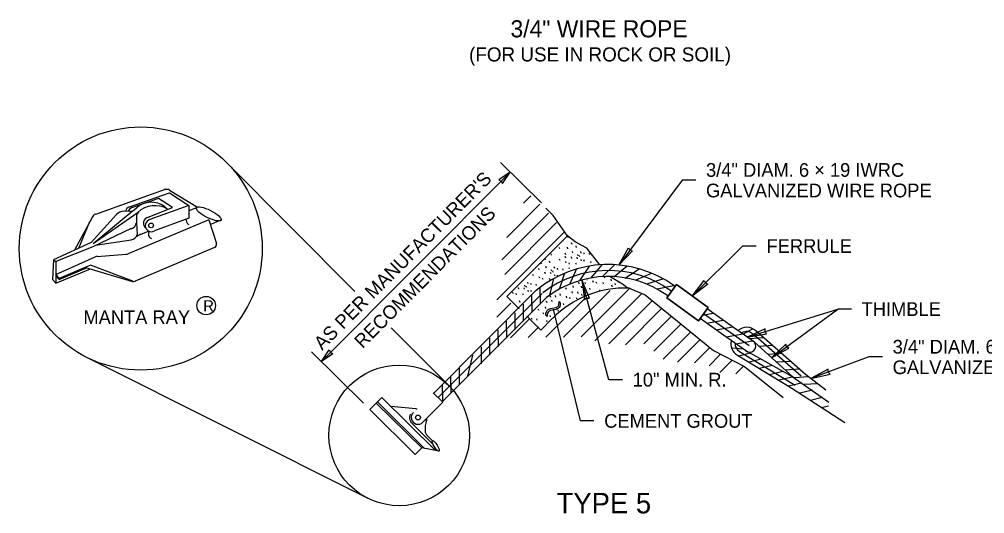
# Model space of a CAD drawing. Extents: x 99861 to 103151, y 100000 to 102076.
# Drawn here: x 101375 to 102504, y 100899 to 101477 of the extents above; entities that cross this region are included whole.
import ezdxf

# ---------------------------------------------------------------- set-up
doc = ezdxf.new("R2010")
doc.units = 0
for name, color, linetype in [('Level 1', 7, 'Continuous'), ('Level 10', 7, 'Continuous'), ('Level 15', 7, 'Continuous'), ('Level 18', 7, 'Continuous'), ('Level 2', 7, 'Continuous'), ('Level 20', 7, 'Continuous'), ('Level 4', 7, 'Continuous'), ('Level 6', 7, 'Continuous'), ('Level 8', 7, 'Continuous')]:
    doc.layers.add(name, color=color, linetype=linetype)

msp = doc.modelspace()

# ---------------------------------------------------------------- linework, layer by layer
at = {"layer": 'Level 1'}
for p, q in [((101859.9, 101040.3), (101979.4, 101160.2)), ((101991.7, 101152.1), (101869.9, 101030.4)), ((102280.2, 101059), (102224.6, 101090.1)), ((102235, 101099.8), (102280.2, 101059)), ((102279.2, 101059.7), (102322.1, 101029.8))]:
    msp.add_line(p, q, dxfattribs=at)
for points in [[(102138, 101159.4), (102136.5, 101160.5)], [(102142.1, 101165.1), (102140.5, 101166.2)], [(102133.9, 101153.7), (102132.5, 101154.7)], [(102234.9, 101099.9), (102206.7, 101119.8), (102179.6, 101138.8)], [(102224.6, 101090.1), (102198.7, 101108.3), (102171.4, 101127.5)], [(102318.3, 101043.9), (102294.8, 101062.2), (102236.6, 101113)], [(102215, 101084.7), (102278.5, 101046.3), (102340.8, 101006)]]:
    msp.add_lwpolyline(points, dxfattribs=at)
for centre, radius, start, end in [((102063.9, 101058.4), 132.3, 54.6068, 129.6692), ((102063.9, 101058.4), 118.3, 54.565, 127.6505), ((102225.8, 101101.5), 15.8, 47.0914, 130.0304), ((102222.7, 101097.9), 15.3, 165.1513, 239.931), ((102229.5, 101095.3), 7.15, 226.812, 38.9693)]:
    msp.add_arc(centre, radius, start, end, dxfattribs=at)
at = {"layer": 'Level 10'}
for p, q in [((101964.9, 101262.3), (101973.5, 101271)), ((101964.9, 101262.3), (101973.5, 101271)), ((101945.2, 101222.3), (101984, 101261.1)), ((101939.4, 101196.1), (101994.2, 101250.9)), ((101942.9, 101179.2), (102003.5, 101239.8)), ((101942.9, 101179.2), (102003.5, 101239.8)), ((101933.5, 101149.4), (102012.7, 101228.7)), ((102011.6, 101105.8), (102066.3, 101160.5)), ((102011.6, 101105.8), (102066.3, 101160.5)), ((102032.2, 101106), (102089.6, 101163.5)), ((101933.5, 101129), (101950, 101145.6)), ((101991, 101105.6), (102036.9, 101151.5)), ((102048.2, 101101.6), (102102.9, 101156.4)), ((102064.8, 101097.9), (102115.3, 101148.4)), ((102064.8, 101097.9), (102115.3, 101148.4)), ((102084.2, 101096.9), (102126.4, 101139.2)), ((101949.5, 101105.1), (101971.8, 101127.1)), ((101949.5, 101105.1), (101971.8, 101127.1)), ((102105.5, 101097.9), (102137.5, 101129.9)), ((101970.4, 101105.3), (101982.1, 101117)), ((102117.4, 101089.4), (102148.6, 101120.6)), ((102117.4, 101089.4), (102148.6, 101120.6)), ((102128.3, 101080), (102159.7, 101111.4)), ((102145.1, 101076.4), (102170.8, 101102.1)), ((102165, 101075.9), (102181.9, 101092.8)), ((102165, 101075.9), (102181.9, 101092.8)), ((102181.8, 101072.3), (102194.9, 101085.4)), ((102194.3, 101064.4), (102208.4, 101078.6)), ((102213.2, 101063), (102222, 101071.8)), ((102213.2, 101063), (102222, 101071.8))]:
    msp.add_line(p, q, dxfattribs=at)
at = {"layer": 'Level 15'}
for p, q in [((101617.7, 101309.7), (101767.7, 101159.3)), ((101985.9, 101262.6), (101937.8, 101309.9)), ((101949.3, 101298.6), (101728.4, 101077.4)), ((102150.3, 101289.2), (102076.2, 101190.1)), ((102166.3, 101289.2), (102150.3, 101289.2)), ((102162.2, 101153.8), (102221.1, 101212.3)), ((102237.1, 101212.3), (102221.1, 101212.3)), ((102064.5, 101056.1), (102033.1, 101172.6)), ((101999.4, 101138.6), (102031.2, 101007.9)), ((102226.6, 101105.8), (102332.3, 101138.6)), ((102255, 101081.8), (102332.3, 101138.6)), ((102348.3, 101138.6), (102332.3, 101138.6)), ((101810.1, 101116.8), (101877.6, 101049.1)), ((101453.5, 101082.3), (101782.6, 100917.5)), ((101777.8, 101028.8), (101717, 101088.7)), ((102368.6, 101082.6), (102300.9, 101057.4)), ((102384.6, 101082.6), (102368.6, 101082.6)), ((102080.5, 101056.1), (102064.5, 101056.1)), ((102047.2, 101007.9), (102031.2, 101007.9))]:
    msp.add_line(p, q, dxfattribs=at)
for points in [[(101949.3, 101298.6), (101936, 101289.7), (101938.7, 101288), (101940.4, 101285.3)], [(102076.2, 101190.1), (102087.5, 101210.1), (102089.2, 101207.5), (102092.3, 101206.6)], [(102033.1, 101172.6), (102036.1, 101149.8), (102038.7, 101151.5), (102041.9, 101151.3)], [(102162.2, 101153.8), (102176.3, 101172), (102177.6, 101169.2), (102180.5, 101167.8)], [(102226.6, 101105.8), (102249.2, 101109.7), (102247.4, 101112.3), (102247.5, 101115.4)], [(101728.4, 101077.4), (101737.3, 101090.8), (101739, 101088.1), (101741.7, 101086.4)], [(102255, 101081.8), (102275.1, 101092.9), (102272.5, 101094.7), (102271.6, 101097.7)], [(102300.9, 101057.4), (102323.4, 101062.6), (102321.3, 101065), (102321.3, 101068.2)]]:
    msp.add_lwpolyline(points, close=True, dxfattribs=at)
for centre, radius in [((101517.1, 101209.4), 142.1), ((101819.4, 100991), 82.2)]:
    msp.add_circle(centre, radius, dxfattribs=at)
at = {"layer": 'Level 2'}
for p, q in [((101515.7, 101259.7), (101509.3, 101254.4)), ((101506.8, 101252.4), (101461.4, 101214.9)), ((101512.8, 101250.6), (101461.4, 101214.9)), ((101582.3, 101257), (101573.2, 101253.3)), ((101460.6, 101246.3), (101439.6, 101207.5)), ((101444.8, 101209.8), (101457.6, 101240.8)), ((101610.9, 101242.4), (101598.5, 101237.3)), ((101526.5, 101229.6), (101517, 101225.9)), ((102016.4, 101224.2), (101945.4, 101153.2)), ((101417.6, 101194.4), (101417.6, 101172.8)), ((101421.6, 101173.3), (101453.5, 101187)), ((101959.9, 101138.9), (101945.4, 101153.2)), ((101985.1, 101114.1), (101968.7, 101130.2)), ((101985.1, 101114.1), (101998.9, 101128.1)), ((101793.1, 101029.3), (101799, 101035.2)), ((101861.8, 100973.3), (101799, 101035.2)), ((101870.5, 101029.8), (101859.2, 101040.9)), ((101785.1, 101021.3), (101793.1, 101029.3)), ((101838.1, 100968.5), (101785.1, 101021.3)), ((101845.9, 100976.4), (101792.6, 101028.8)), ((101849.1, 100975.8), (101793.9, 101030.1)), ((101838.9, 101022), (101809.7, 101024.6)), ((101847.1, 101006.3), (101870.5, 101029.8)), ((101832.9, 101006.5), (101858.8, 100980.9)), ((101858.4, 100984.6), (101852.6, 100990.3)), ((101838.1, 100968.5), (101845.9, 100976.4)), ((101866, 100972.5), (101845.9, 100976.4))]:
    msp.add_line(p, q, dxfattribs=at)
for points in [[(101464.5, 101249.7), (101544.7, 101278.2)], [(101504.1, 101258.2), (101550.7, 101274.5), (101573.2, 101259.7), (101527.9, 101243.2)], [(101550.9, 101277.6), (101583.6, 101257.9)], [(101525.6, 101246), (101554.1, 101257.2), (101537.8, 101267.8), (101506.4, 101256.8)], [(101573.2, 101259.7), (101573.2, 101245), (101533.3, 101230.2)], [(101488.6, 101249), (101459.2, 101216.5), (101415.1, 101196.2)], [(101504.5, 101252.8), (101497.5, 101252.9)], [(102016, 101224.6), (101999.4, 101248.1), (101990.8, 101256.7)], [(101596.8, 101243), (101502.4, 101203.2)], [(101512.1, 101246.8), (101512.1, 101239.8)], [(101512.1, 101239.8), (101512.9, 101225.9)], [(101569.9, 101243.8), (101569.9, 101243.6)], [(101572.5, 101238), (101573.4, 101237.3)], [(101596.8, 101243), (101605.6, 101215.3)], [(101505.8, 101232.6), (101460.9, 101211.4), (101417.6, 101194.4)], [(101526, 101227.2), (101526, 101226.9)], [(101505.8, 101219.3), (101464.2, 101213)], [(101528.7, 101221.4), (101529.5, 101220.7)], [(102053.9, 101190.3), (102038.7, 101209.7), (102025.3, 101217.4), (102016.4, 101224.2)], [(101466.3, 101200.2), (101500.1, 101202.6)], [(101603.4, 101210.4), (101510.6, 101171.3)], [(101415.1, 101196.2), (101413.8, 101173), (101417.6, 101168.8)], [(101415.1, 101196.2), (101417.6, 101194.4)], [(101417.6, 101179.1), (101463.9, 101199.6)], [(101417.6, 101172.8), (101417.6, 101168.8), (101458.3, 101185.5)], [(101417.8, 101181.8), (101417.6, 101179.1), (101421.5, 101174.9)], [(101507.7, 101171.2), (101458.3, 101189.8), (101421.6, 101174.5)], [(101452.6, 101187.2), (101507.4, 101170.9)], [(101421.6, 101174.5), (101421.6, 101173.3), (101417.6, 101177.5)], [(101417.6, 101172.8), (101417.6, 101170.7)], [(102066, 101176.6), (102080.5, 101168.3), (102085.6, 101164.3), (102107, 101155.3)], [(102107, 101155.3), (102187, 101090.1), (102223.5, 101071.5), (102268.5, 101035.4)]]:
    msp.add_lwpolyline(points, dxfattribs=at)
for centre, radius in [((101529.2, 101236.4), 2.74), ((101593.6, 101142.7), 10.8), ((101841.4, 101011.9), 2.88)]:
    msp.add_circle(centre, radius, dxfattribs=at)
for centre, radius, start, end in [((101547.2, 101271.4), 7.2, 59.0362, 109.5852), ((101505.7, 101252.1), 6.32, 104.778, 172.4401), ((101533.7, 101230.6), 28.9, 59.6054, 133.9446), ((101529.2, 101236.4), 27, 45, 120.2173), ((101466.9, 101242.9), 7.2, 109.6041, 151.5571), ((101497.5, 101240.9), 12, 90, 137.7927), ((101508.3, 101251), 6.06, 107.9609, 162.1611), ((101504.7, 101260), 7.2, 268.9234, 309.516), ((101519.3, 101246.8), 7.2, 131.5306, 180), ((101508.7, 101256.5), 7.2, 304.7847, 313.9446), ((101503.4, 101241.1), 8.84, 285.703, 351.7847), ((101527.3, 101238.9), 7.15, 100.4083, 234.4437), ((101529.5, 101236.2), 7.15, 100.4083, 301.5442), ((101577.1, 101243.6), 7.2, 180, 230.5368), ((101504.3, 101228.1), 8.88, 279.9313, 346.013), ((101524.3, 101207.3), 20, 110.8825, 134.4879), ((101533.2, 101226.9), 7.2, 158.16, 230.5368), ((101601.7, 101214.1), 4, 292.8671, 17.488), ((101499.6, 101209.8), 7.2, 274.0406, 292.8671), ((101466.8, 101193.1), 7.2, 94.0406, 113.9625), ((101508.5, 101174.8), 4, 253.4312, 296.6388), ((101509.1, 101175), 4, 249.444, 292.8671), ((102084.3, 101041.9), 121.3, 88.2521, 134.7188), ((101839.6, 101029.2), 7.2, 264.818, 276.1978), ((101841.7, 101011.9), 10.2, 156.5618, 234.4179), ((101841.4, 101011.9), 7.92, 133.3092, 315.1068), ((101841.7, 101011.9), 10.2, 339.9114, 354.6773), ((101877.4, 100999), 27.8, 160.2069, 184.7482), ((101859.6, 100997.4), 10, 184.1123, 225.4559)]:
    msp.add_arc(centre, radius, start, end, dxfattribs=at)
for centre, major_axis, ratio in [((101596.7, 101249.8), (14.4, -7.2), 0.282353), ((101862.2, 100978.6), (3.77, -6.04), 0.269557)]:
    msp.add_ellipse(centre, major_axis=major_axis, ratio=ratio, dxfattribs=at)
at = {"layer": 'Level 20'}
for p, q in [((102006, 101143.6), (102006.6, 101147.3)), ((102006.6, 101147.3), (102007.8, 101145.5)), ((102007.8, 101145.5), (102007.7, 101143.4)), ((101991.1, 101133.6), (101991.6, 101135.3)), ((101991.6, 101135.3), (101992.5, 101136.8)), ((101992.5, 101136.8), (101993.8, 101138)), ((101993, 101134), (101992.6, 101132.3)), ((101993.7, 101135.1), (101993, 101134)), ((101994.7, 101136.1), (101993.7, 101135.1)), ((101993.8, 101138), (101996.2, 101139.2)), ((101996.4, 101136.9), (101994.7, 101136.1)), ((101996.2, 101139.2), (102000.5, 101140)), ((101998.9, 101137.4), (101996.4, 101136.9)), ((102003, 101138), (101998.9, 101137.4)), ((102000.5, 101140), (102002.9, 101140.4)), ((102002.9, 101140.4), (102004.3, 101141.1)), ((102005.2, 101139.2), (102003, 101138)), ((102004.3, 101141.1), (102005.2, 101142.1)), ((102005.2, 101142.1), (102006, 101143.6)), ((102006.4, 101140.3), (102005.2, 101139.2)), ((102007.2, 101141.7), (102006.4, 101140.3)), ((102007.7, 101143.4), (102007.2, 101141.7)), ((101991.1, 101131.6), (101991.1, 101133.6)), ((101992.3, 101129.9), (101991.1, 101131.6)), ((101992.6, 101132.3), (101992.3, 101129.9))]:
    msp.add_line(p, q, dxfattribs=at)
at = {"layer": 'Level 4'}
for p, q in [((102044, 101175.2), (102056.7, 101190.4)), ((102044, 101175.2), (102056.7, 101190.4)), ((102057.3, 101176.5), (102071.4, 101190.5)), ((102057.3, 101176.5), (102071.4, 101190.5)), ((102007.1, 101162), (102013.2, 101180.8)), ((102007.1, 101162), (102013.2, 101180.8)), ((102019.1, 101167.7), (102027, 101185.9)), ((102019.1, 101167.7), (102027, 101185.9)), ((102031, 101172.4), (102042.1, 101188.7)), ((102031, 101172.4), (102042.1, 101188.7)), ((102070.6, 101176.4), (102085.9, 101189)), ((102070.6, 101176.4), (102085.8, 101188.8)), ((102083.9, 101174.8), (102100.3, 101185.9)), ((102083.9, 101174.8), (102100.3, 101185.9)), ((102096.4, 101172.6), (102114.6, 101180.4)), ((102096.4, 101172.6), (102114.6, 101180.4)), ((101995.7, 101155), (102000.1, 101174.4)), ((101995.7, 101155), (102000.1, 101174.4)), ((102109, 101168), (102127.8, 101174.1)), ((102109, 101168), (102127.8, 101174.1)), ((101986.7, 101157), (101864.9, 101035.3)), ((101984.1, 101164.3), (101984.2, 101144.5)), ((102121, 101162.1), (102140.3, 101166.3)), ((102121, 101162.1), (102140.3, 101166.3)), ((101974.2, 101154.3), (101974.4, 101134.5)), ((101954.6, 101134.4), (101954.7, 101114.6)), ((101964.4, 101144.4), (101964.5, 101124.6)), ((101944.7, 101124.5), (101944.8, 101104.7)), ((102174.3, 101131.5), (102186.8, 101133.7)), ((102178.8, 101122.3), (102198.3, 101125.7)), ((101934.9, 101114.5), (101935, 101094.7)), ((102190.3, 101114.2), (102209.8, 101117.7)), ((102233, 101115.5), (102221.8, 101109.1)), ((101925, 101104.6), (101925.1, 101084.8)), ((102201.7, 101106.2), (102221.2, 101109.6)), ((102213.2, 101098.1), (102232.7, 101101.5)), ((102245.6, 101105.1), (102228.7, 101103.9)), ((102289.6, 101060.1), (102233.3, 101109.2)), ((101915.2, 101094.6), (101915.3, 101074.8)), ((102222.2, 101091.8), (102208.3, 101092.9)), ((102217.6, 101089), (102282.5, 101049.7)), ((102256.2, 101095.9), (102240.5, 101094.8)), ((101905.3, 101084.6), (101899.4, 101060.3)), ((102230.2, 101087), (102216.8, 101083.7)), ((102242.8, 101079.9), (102228.7, 101076.4)), ((102266.7, 101086.7), (102250.7, 101085.6)), ((102277.3, 101077.5), (102260.9, 101076.4)), ((101889.4, 101070.1), (101889.5, 101050.3)), ((102255.5, 101072.8), (102240.7, 101069.2)), ((102287.8, 101068.3), (102270.9, 101067.1)), ((101879.6, 101060.2), (101879.7, 101040.4)), ((102268.1, 101065.7), (102252.7, 101061.9)), ((102280.5, 101059.4), (102264, 101055.4)), ((102298.5, 101059.3), (102281.5, 101058.1)), ((101869.7, 101050.2), (101869.9, 101030.4)), ((102289.9, 101052.2), (102274.9, 101048.5)), ((102303, 101044), (102287.9, 101040.3)), ((102308.6, 101051.4), (102293.1, 101050.4)), ((102314, 101035.3), (102300.5, 101031.9)), ((102321.6, 101025.3), (102313.5, 101023.3))]:
    msp.add_line(p, q, dxfattribs=at)
msp.add_lwpolyline([(102228.6, 101095.8), (102202.7, 101114.1), (102175.5, 101133.1)], dxfattribs=at)
for centre, radius, start, end in [((102063.9, 101058.4), 125.3, 54.565, 127.6505), ((102225.8, 101101.5), 10.8, 47.0914, 120.8742), ((102222.7, 101097.9), 10.3, 173.2357, 239.931)]:
    msp.add_arc(centre, radius, start, end, dxfattribs=at)
at = {"layer": 'Level 6'}
for p, q in [((102132.4, 101151.6), (102143.6, 101167.2)), ((102143.6, 101167.2), (102180.8, 101140.5)), ((102169.5, 101124.9), (102132.4, 101151.6)), ((102180.8, 101140.5), (102169.5, 101124.9))]:
    msp.add_line(p, q, dxfattribs=at)
msp.add_lwpolyline([(102169.5, 101124.9), (102180.8, 101140.5), (102143.6, 101167.2), (102132.4, 101151.6), (102169.5, 101124.9)], dxfattribs=at)
at = {"layer": 'Level 8'}
for p, q in [((102011.2, 101217.5), (102010.8, 101218.7)), ((102017.3, 101221.7), (102016.7, 101223.5)), ((102021.7, 101214.2), (102021.1, 101215.9)), ((101997.6, 101201.5), (101997.1, 101203.2)), ((102007.3, 101209), (102006.7, 101210.7)), ((102014.3, 101202.2), (102013.7, 101203.9)), ((102016.7, 101209), (102016.1, 101210.8)), ((102022.7, 101204.3), (102022.1, 101206.1)), ((102026.9, 101210.6), (102026.3, 101212.4)), ((102028.9, 101200.8), (102028.3, 101202.5)), ((102032.4, 101204.1), (102031.8, 101205.9)), ((102036.1, 101202.6), (102035.5, 101204.4)), ((102042.2, 101201.9), (102041.7, 101203.6)), ((101985.7, 101191.1), (101985.1, 101192.9)), ((101990.7, 101196.3), (101990.1, 101197.9)), ((101995.9, 101192.7), (101995.3, 101194.5)), ((102007.5, 101195.2), (102006.9, 101196.9)), ((102014.2, 101198.2), (102013.6, 101199.9)), ((102014.9, 101192.5), (102014.3, 101194.2)), ((102018.8, 101191), (102018.2, 101192.8)), ((102021.4, 101197.8), (102020.9, 101199.6)), ((102026.8, 101190.6), (102026.2, 101192.3)), ((102028.1, 101197.5), (102027.5, 101199.3)), ((102030.6, 101199.5), (102030, 101201.2)), ((102032.8, 101194.9), (102032.2, 101196.6)), ((102036.1, 101194.4), (102035.5, 101196.2)), ((102044.1, 101192.5), (102043.6, 101194.3)), ((101983.3, 101184.3), (101982.7, 101186)), ((101990.4, 101179.9), (101989.9, 101181.7)), ((101991.7, 101186.4), (101991.1, 101188.2)), ((101997.1, 101179.7), (101996.5, 101181.4)), ((101997.9, 101182.9), (101997.3, 101184.6)), ((101999.6, 101181.6), (101999, 101183.3)), ((102001.4, 101186.2), (102000.8, 101188)), ((102005.1, 101184.8), (102004.5, 101186.5)), ((102011.2, 101184), (102010.7, 101185.7)), ((102018.6, 101185.7), (102018.2, 101187)), ((101970.4, 101168.4), (101969.8, 101170.1)), ((101974.1, 101166.9), (101973.5, 101168.6)), ((101976.5, 101177.3), (101975.9, 101179)), ((101980.2, 101166.1), (101979.7, 101167.8)), ((101983.9, 101174.6), (101983.3, 101176.3)), ((101987.8, 101173.1), (101987.2, 101174.9)), ((101995.8, 101172.7), (101995.2, 101174.5)), ((102001.8, 101177), (102001.2, 101178.7)), ((102005.1, 101176.5), (102004.5, 101178.3)), ((102029.9, 101168.2), (102029.4, 101170)), ((102037.4, 101168), (102036.9, 101169.7)), ((102039.2, 101172.5), (102039.1, 101172.8)), ((102046.5, 101169.8), (102046, 101171.6)), ((102050.5, 101168.4), (102049.9, 101170.1)), ((102058.4, 101168), (102057.9, 101169.7)), ((102059.8, 101174.9), (102059.5, 101175.8)), ((102067.8, 101171.8), (102067.2, 101173.5)), ((102072.5, 101166.9), (102071.9, 101168.7)), ((102075.8, 101169.9), (102075.7, 101170.4)), ((101952.9, 101156.7), (101952.3, 101158.4)), ((101956.8, 101155.2), (101956.2, 101157)), ((101959.4, 101162), (101958.9, 101163.8)), ((101964.8, 101154.8), (101964.2, 101156.6)), ((101966.1, 101161.8), (101965.5, 101163.5)), ((101966.9, 101165), (101966.4, 101166.7)), ((101968.6, 101163.7), (101968, 101165.4)), ((101970.8, 101159.1), (101970.2, 101160.8)), ((101974.1, 101158.6), (101973.5, 101160.4)), ((102015, 101161.6), (102014.4, 101163.4)), ((102022.1, 101157.3), (102021.6, 101159)), ((102023.4, 101163.8), (102022.8, 101165.6)), ((102028.8, 101157), (102028.2, 101158.8)), ((102033.1, 101163.6), (102032.5, 101165.4)), ((102036.8, 101162.1), (102036.2, 101163.9)), ((102042.9, 101161.3), (102042.4, 101163.1)), ((102054.4, 101159.5), (102053.9, 101161.2)), ((102068.8, 101164.7), (102068.3, 101166.4)), ((102073.5, 101162.8), (102073.5, 101162.9)), ((102085.7, 101163.6), (102085.5, 101164.2)), ((101960.8, 101146.3), (101960.2, 101148.1)), ((101992.4, 101145.9), (101991.8, 101147.7)), ((101996.6, 101152.2), (101996, 101153.9)), ((101998.4, 101147.5), (101997.9, 101149.2)), ((102002.7, 101152.6), (102002.1, 101154.3)), ((102008.2, 101154.6), (102007.6, 101156.4)), ((102015.5, 101151.9), (102015, 101153.7)), ((102019.5, 101150.5), (102018.9, 101152.2)), ((102027.4, 101150.1), (102026.9, 101151.8)), ((102033.5, 101154.3), (102032.9, 101156.1)), ((102036.8, 101153.9), (102036.2, 101155.7)), ((101977.2, 101136.7), (101977, 101137.2)), ((101982.6, 101136.8), (101982, 101138.5)), ((101984, 101143.8), (101983.8, 101144.1)), ((101988.5, 101132.6), (101987.9, 101134.3)), ((101991.1, 101139.4), (101990.6, 101141.1)), ((102005.8, 101136), (102005.2, 101137.8)), ((102011.9, 101143.4), (102011.4, 101145.2)), ((101971.1, 101128), (101970.5, 101129.6)), ((101974.8, 101126.3), (101974.2, 101128.1)), ((101980.9, 101125.5), (101980.4, 101127.3)), ((101992.5, 101123.7), (101991.9, 101125.4)), ((101996.5, 101129.4), (101995.9, 101131.2)), ((101982.4, 101117.5), (101982.3, 101117.9))]:
    msp.add_line(p, q, dxfattribs=at)

# ---------------------------------------------------------------- texts
at = {"layer": 'Level 18'}
for s, height, p in [('3/4" WIRE ROPE ', 20, (101949.6, 101456.2)), ('(FOR USE IN ROCK OR SOIL)', 16.5, (101901.1, 101428)), ('MANTA RAY ', 16, (101450, 101121.1)), ('TYPE 5', 24, (102003.5, 100899.8))]:
    msp.add_text(s, height=height, dxfattribs=at).set_placement(p)
at = {"layer": 'Level 2'}
msp.add_text('R', height=13, dxfattribs=at).set_placement((101590.2, 101135.9))
at = {"layer": 'Level 20'}
for s, p in [('3/4" DIAM. 6 × 19 IWRC ', (102178.3, 101293.2)), ('GALVANIZED WIRE ROPE', (102178.3, 101269.2)), ('FERRULE', (102249.1, 101204.3)), ('THIMBLE', (102360.3, 101130.6)), ('3/4" DIAM. 6 × 19 IWRC ', (102396.6, 101086.6)), ('GALVANIZED WIRE ROPE', (102396.6, 101062.6)), ('10" MIN. R.', (102092.5, 101048.1)), ('CEMENT GROUT', (102059.2, 100999.9))]:
    msp.add_text(s, height=16, dxfattribs=at).set_placement(p)
for s, p in [("AS PER MANUFACTURER'S ", (101729.3, 101089.7)), ('RECOMMENDATIONS', (101776.5, 101091.6))]:
    msp.add_text(s, height=16, rotation=45.0414, dxfattribs=at).set_placement(p)

doc.saveas('drawing.dxf')
